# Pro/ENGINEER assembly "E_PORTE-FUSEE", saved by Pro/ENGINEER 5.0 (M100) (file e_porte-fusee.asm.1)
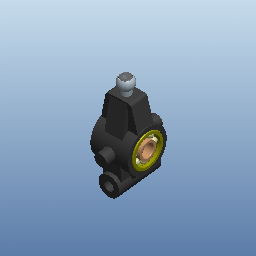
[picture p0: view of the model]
Units: millimeter Newton Second (mmNs); MM, TONNE, HOURS

Other components: 80126000-PORTE_MOYEU_AR_A0, ROULEMENT_BC_8X22X7, ROULEMENT_BC_8X22X7, 80025000-ROTULE_STD_A0, VIS_CHC_M-4X16

Other named items: 80126000-PORTE_MOYEU_AR_01, A-DROITE, A-DESSUS, A-FACE, A-R0, ACS0, ACS1, ACS2

Family table entries: GENERIC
